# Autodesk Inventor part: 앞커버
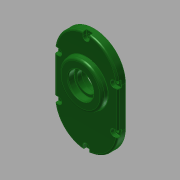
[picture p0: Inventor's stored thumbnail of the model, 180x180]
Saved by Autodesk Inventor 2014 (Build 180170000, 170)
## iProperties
Created: 2016-12
Part Number: 앞커버
Material: 일반
Document SubType Name: Modeling
Designer: mduedu
Density: 1 g/cm^3
Appearance: 매끄러움 - 짙은 산림 녹색
Mass: 97.1027 g
Surface Area: 259.14 cm^2
Volume: 97.1027 cm^3
Author: mduedu
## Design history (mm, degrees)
sketch "스케치1"
  geometry: L1 (40, -25)-(40, 25); L2 (-40, 25)-(-40, -25); L3 (-40, -25)-(40, 25); L4 (40, -25)-(-40, 25); A1 r 40 centre (0, 25) between (40, 25) and (-40, 25); A2 r 40 centre (0, -25) between (-40, -25) and (40, -25); 1 further point
  constraints: 8 end point, 4 point on circle, 4 tangent, 2 centre point, 2 midpoint, 1 parallel, 1 vertical
  dimensions: "d0" = 130 dimension on A2 A1; "d2" = 80 distance between parallel lines of L1 L2
extrude "돌출1" new body sketch "스케치1" distance "d3" = 10; taper "d4" = 0 deg
sketch "스케치2"
  geometry: C1 r 21 at (0, 11); 1 further point
  constraints: 1 centre point, 1 vertical alignment
  dimensions: "d5" = 42 diameter of C1; "d7" = 11 distance of C1.centre point (0, 0)
extrude "돌출2" join sketch "스케치2" distance "d8" = 7; taper "d9" = 0 deg
sketch "스케치3"
  geometry: C1 r 15 at (0, -33.1); C2 r 21 at (0, 11) reference; 1 further point
  constraints: 1 centre point, 1 vertical alignment
  dimensions: "d10" = 30 diameter of C1; "d71" = 44.1 distance of C1.centre C2.centre
extrude "돌출3" join sketch "스케치3" distance "d12" = 7; taper "d13" = 0 deg
sketch "스케치4"
  geometry: C1 r 28 at (0, 11); A1 r 21 centre (0, 11) between (8.978, -7.984) and (-8.978, -7.984) reference; 1 further point
  constraints: 1 centre point, 1 coincident
  dimensions: "d14" = 56 diameter of C1
extrude "돌출4" join sketch "스케치4" distance "d15" = 7; taper "d16" = -5 deg
hole "구멍1" diameter "d19" = 35; stored, may be unused: countersink angle "d23" = 90 deg, drill point angle "d25" = 0 deg; dims "d17" = 10, "d18" = 10, "d20" = 6, "d21" = 4, "d22" = 2, "d24" = 10
hole "구멍2" diameter "d28" = 22; stored, may be unused: countersink angle "d32" = 90 deg, drill point angle "d34" = 0 deg; dims "d26" = 10, "d27" = 10, "d29" = 6, "d30" = 4, "d31" = 2, "d33" = 7
hole "구멍3" diameter "d37" = 19; stored, may be unused: countersink angle "d41" = 90 deg, drill point angle "d43" = 0 deg; dims "d35" = 10, "d36" = 10, "d38" = 6, "d39" = 4, "d40" = 2, "d42" = 1
hole "구멍4" diameter "d46" = 32; stored, may be unused: countersink angle "d50" = 90 deg, drill point angle "d52" = 0 deg; dims "d44" = 10, "d45" = 10, "d47" = 6, "d48" = 4, "d49" = 2, "d51" = 8
hole "구멍5" diameter "d55" = 25; stored, may be unused: countersink angle "d59" = 90 deg, drill point angle "d61" = 0 deg; dims "d53" = 10, "d54" = 10, "d56" = 6, "d57" = 4, "d58" = 2, "d60" = 8
fillet "모깎기1" dims "d62" = 0.3
fillet "모깎기2" dims "d63" = 2
chamfer "모따기1" distance "d64" = 1; stored, may be unused: second distance "d65" = 2, angle "d66" = 45 deg
fillet "모깎기4" dims "d68" = 2
fillet "모깎기5" dims "d69" = 0.3
fillet "모깎기6" dims "d70" = 2
sketch "스케치5"
  geometry: L1 (-40, 25)-(-40, -25) reference; L2 (40, -25)-(40, 25) reference; L3 (35, 25)-(35, -25); L4 (-35, -25)-(-35, 25); A1 r 40 centre (0, 25) between (40, 25) and (-40, 25) reference; A2 r 40 centre (0, -25) between (-40, -25) and (40, -25) reference; A3 r 35 centre (0, 25) between (35, 25) and (-35, 25); A4 r 35 centre (0, -25) between (-35, -25) and (35, -25); 2 further points
  constraints: 5 point on circle, 4 end point, 2 centre point, 1 vertical alignment, 3 other
  dimensions: "d72" = 5 distance between parallel lines of L2 L3
sketch "스케치7"
  geometry: 1 further point
hole "구멍7" sketch "스케치7" at (0, 60) diameter "d80" = 4.5; stored, may be unused: countersink angle "d84" = 90 deg, drill point angle "d86" = 0 deg; dims "d81" = 6, "d82" = 8, "d83" = 4.6, "d85" = 8
sketch "스케치9"
  geometry: L1 (-4, 0)-(4, 0); L2 (4, 0)-(4, 5); L3 (4, 5)-(-4, 5); L4 (-4, 5)-(-4, 0); C1 r 2.25 at (0, 0) reference; A1 r 40 centre (0, -35) between (40, -35) and (-40, -35) reference; 2 further points
  constraints: 8 end point, 2 parallel, 2 vertical, 1 horizontal, 1 horizontal alignment, 1 perpendicular, 1 tangent, 1 other
extrude "돌출6" cut sketch "스케치9" stored distance "d96" = 3; taper "d97" = 0 deg
fillet "모깎기7" dims "d98" = 0.3
fillet "모깎기8" dims "d99" = 0.3
fillet "모깎기9" dims "d100" = 3
node "솔리드1"
pattern_linear "직사각형 패턴1"
node "투영된 루프1"
